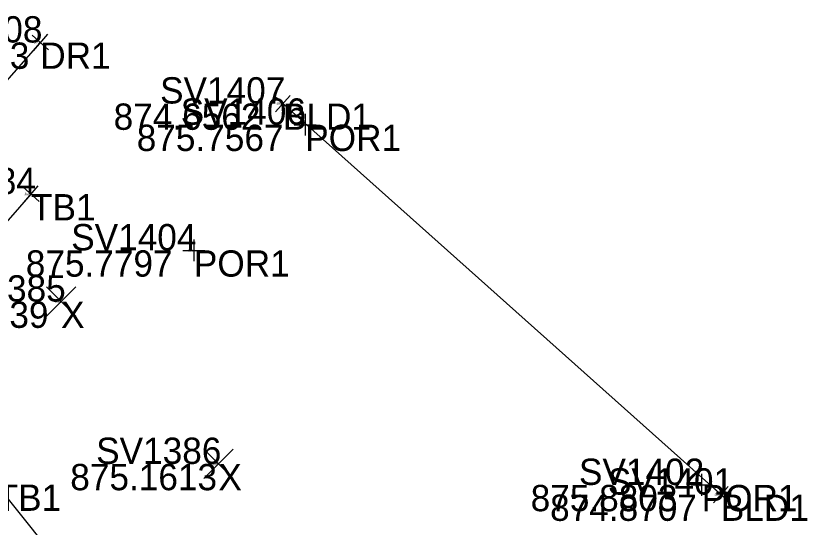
# Model space of a CAD drawing. Extents: x 1469677 to 1493262, y 375219 to 389293.
# Drawn here: x 1480131.95 to 1480168.03, y 379504.97 to 379528.29 of the extents above; entities that cross this region are included whole.
import ezdxf

# ---------------------------------------------------------------- set-up
doc = ezdxf.new("R2010")
doc.units = 0
for name, color, linetype in [('Border', 7, 'Continuous'), ('DV_X_Text', 7, 'Continuous'), ('GK_Visualization', 7, 'Continuous'), ('PNTELEV', 7, 'Continuous'), ('PV_X_Curb', 7, 'Continuous'), ('RW_P_Esmt_SW', 7, 'Continuous'), ('RW_P_Esmt_U', 7, 'Continuous'), ('Text Border', 7, 'Continuous')]:
    doc.layers.add(name, color=color, linetype=linetype)

msp = doc.modelspace()

# ---------------------------------------------------------------- linework, layer by layer
at = {"layer": 'Border'}
msp.add_lwpolyline([(1480164.096, 379506.456), (1480144.131, 379524.291)], dxfattribs=at)
at = {"layer": 'PNTELEV'}
for p, q in [((1480133.443, 379526.743), (1480132.692, 379527.403)), ((1480133.398, 379527.448), (1480132.737, 379526.697)), ((1480133.067, 379527.073), (1480133.067, 379527.073)), ((1480144.504, 379523.958), (1480143.758, 379524.624)), ((1480143.798, 379523.918), (1480144.464, 379524.664)), ((1480144.131, 379524.291), (1480144.131, 379524.291)), ((1480145.147, 379523.825), (1480145.147, 379522.825)), ((1480144.647, 379523.325), (1480145.647, 379523.325)), ((1480145.147, 379523.325), (1480145.147, 379523.325)), ((1480132.268, 379520.486), (1480133.021, 379519.829)), ((1480132.316, 379519.781), (1480132.973, 379520.534)), ((1480132.645, 379520.158), (1480132.645, 379520.158)), ((1480140.07, 379518.094), (1480140.07, 379517.094)), ((1480139.57, 379517.594), (1480140.57, 379517.594)), ((1480140.07, 379517.594), (1480140.07, 379517.594)), ((1480163.22, 379507.395), (1480163.22, 379506.395)), ((1480162.72, 379506.895), (1480163.72, 379506.895)), ((1480163.22, 379506.895), (1480163.22, 379506.895)), ((1480164.468, 379506.123), (1480163.723, 379506.789)), ((1480163.762, 379506.083), (1480164.429, 379506.829)), ((1480164.096, 379506.456), (1480164.096, 379506.456))]:
    msp.add_line(p, q, dxfattribs=at)
at = {"layer": 'PV_X_Curb'}
msp.add_lwpolyline([(1480139.808, 379491.765), (1480141.427, 379493.056), (1480141.937, 379493.998), (1480140.138, 379495.555), (1480131.076, 379506.913), (1480127.878, 379509.549), (1480127.257, 379513.845), (1480127.148, 379513.859), (1480132.645, 379520.158)], dxfattribs=at)
at = {"layer": 'RW_P_Esmt_U'}
for p, q in [((1480133.349, 379514.59), (1480134.683, 379515.925)), ((1480133.349, 379515.925), (1480134.683, 379514.59)), ((1480140.521, 379507.186), (1480141.855, 379508.521)), ((1480140.521, 379508.521), (1480141.855, 379507.186))]:
    msp.add_line(p, q, dxfattribs=at)
at = {"layer": 'Text Border'}
msp.add_lwpolyline([(1480133.067, 379527.073), (1480119.167, 379511.259), (1480119.484, 379509.791), (1480117.607, 379507.506), (1480116.47, 379506.886), (1480115.369, 379506.533)], dxfattribs=at)

# ---------------------------------------------------------------- texts
at = {"layer": 'DV_X_Text'}
for s, height, p in [('873.7713', 1.2, (1480125.878, 379525.873)), ('873.77', 0.06, (1480132.787, 379527.013)), ('874.6562', 1.2, (1480136.412, 379523.091)), ('874.66', 0.06, (1480143.846, 379524.231)), ('875.7567', 1.2, (1480137.465, 379522.125)), ('875.76', 0.06, (1480144.864, 379523.265)), ('874.60', 0.06, (1480132.358, 379520.098)), ('875.7797', 1.2, (1480132.407, 379516.394)), ('875.78', 0.06, (1480139.79, 379517.534)), ('874.9139', 1.2, (1480126.751, 379514.058)), ('874.91', 0.06, (1480133.757, 379515.198)), ('875.1613', 1.2, (1480134.434, 379506.653)), ('875.16', 0.06, (1480140.928, 379507.793)), ('875.8803', 1.2, (1480155.425, 379505.695)), ('875.88', 0.06, (1480162.939, 379506.835)), ('874.8707', 1.2, (1480156.31, 379505.256)), ('874.87', 0.06, (1480163.815, 379506.396))]:
    msp.add_text(s, height=height, dxfattribs=at).set_placement(p)
at = {"layer": 'GK_Visualization'}
for s, p in [('DR1', (1480133.067, 379525.873)), ('BLD1', (1480144.131, 379523.091)), ('POR1', (1480145.147, 379522.125)), ('TB1', (1480132.645, 379518.958)), ('POR1', (1480140.07, 379516.394)), ('X', (1480134.016, 379514.058)), ('X', (1480141.188, 379506.653)), ('TB1', (1480131.076, 379505.713)), ('POR1', (1480163.22, 379505.695)), ('BLD1', (1480164.096, 379505.256))]:
    msp.add_text(s, height=1.2, dxfattribs=at).set_placement(p)
at = {"layer": 'RW_P_Esmt_SW'}
for s, height, p in [('SV1408', 1.2, (1480127.456, 379527.073)), ('SV1408', 0.06, (1480132.786, 379527.073)), ('SV1407', 1.2, (1480138.529, 379524.291)), ('SV1406', 1.2, (1480139.469, 379523.325)), ('SV1407', 0.06, (1480143.851, 379524.291)), ('SV1406', 0.06, (1480144.863, 379523.325)), ('SV1384', 1.2, (1480127.156, 379520.158)), ('SV1384', 0.06, (1480132.371, 379520.158)), ('SV1404', 1.2, (1480134.477, 379517.594)), ('SV1404', 0.06, (1480139.79, 379517.594)), ('SV1385', 1.2, (1480128.518, 379515.258)), ('SV1385', 0.06, (1480133.741, 379515.258)), ('SV1386', 1.2, (1480135.614, 379507.853)), ('SV1402', 1.2, (1480157.627, 379506.895)), ('SV1386', 0.06, (1480140.909, 379507.853)), ('SV1401', 1.2, (1480158.945, 379506.456)), ('SV1402', 0.06, (1480162.94, 379506.895)), ('SV1401', 0.06, (1480163.838, 379506.456))]:
    msp.add_text(s, height=height, dxfattribs=at).set_placement(p)

doc.saveas('drawing.dxf')
